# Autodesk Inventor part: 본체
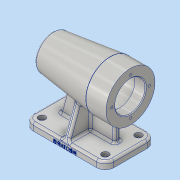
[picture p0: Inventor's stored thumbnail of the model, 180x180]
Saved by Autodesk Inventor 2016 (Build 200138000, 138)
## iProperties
Created: 2018-09
Part Number: 본체
Material: 알루미늄 6061
Document SubType Name: Modeling
Designer: 605-17
Density: 2.7 g/cm^3
Appearance: 알루미늄 - 평지
Mass: 731.151 g
Surface Area: 667.911 cm^2
Volume: 270.797 cm^3
Author: 605-17
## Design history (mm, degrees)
sketch "스케치2"
  geometry: L1 (-56, 35)-(56, 35); L2 (56, 35)-(56, -35); L3 (56, -35)-(-56, -35); L4 (-56, -35)-(-56, 35); 5 further points
  constraints: 8 end point, 4 horizontal alignment, 4 midpoint, 4 vertical alignment, 2 parallel, 1 horizontal, 1 perpendicular
  dimensions: "d0" = 112 distance of L1.start L1.end; "d1" = 70 distance of L3.end L1.start
extrude "돌출1" new body sketch "스케치2" distance "d2" = 10; taper "d3" = 0 deg
sketch "스케치3"
  geometry: L1 (56, 0)-(56, 10) reference; L2 (56, 74)-(-56, 74); L3 (-56, 74)-(-56, 108); L4 (-56, 108)-(-28, 108); L5 (-28, 108)-(52.27, 98.144); L6 (-56, 95)-(-41, 95); L7 (-41, 95)-(-41, 98); L8 (-41, 98)-(13, 98); L9 (13, 98)-(13, 95); L10 (13, 95)-(25, 95); L11 (25, 95)-(25, 91.5); L12 (25, 91.5)-(43, 91.5); L13 (43, 91.5)-(43, 90); L14 (43, 90)-(47, 90); L15 (47, 90)-(47, 84.5); L16 (47, 84.5)-(50, 84.5); L17 (50, 84.5)-(50, 74); A1 r 80 centre (-24, 74) between (52.27, 49.856) and (52.27, 98.144); 1 further point
  constraints: 32 end point, 11 perpendicular, 4 point on line, 3 point on circle, 2 vertical alignment, 1 centre point, 1 collinear, 1 horizontal, 1 horizontal alignment, 1 vertical
  dimensions: "d6" = 112 distance of L2.start L2.end; "d7" = 74 vertical distance of L2.start point (0, 0); "d9" = 7 deg angle of L5 L4; "d10" = 68 diameter of L4 L2; "d11" = 28 distance of L3.end L4.end; "d12" = 80 radius of A1; "d15" = 42 diameter of L6 L2; "d16" = 54 distance of L7.end L8.end; "d17" = 18 distance of L11.end L12.end; "d18" = 35 diameter of L12 L2; "d19" = 32 diameter of L14 L2; "d20" = 21 diameter of L16 L2; "d21" = 3 distance of L15.end L16.end; "d22" = 4 distance of L13.end L14.end; "d104" = 12 distance of L9.end L10.end; "d105" = 48 diameter of L8 L2; "d106" = 15 distance of L6.start L6.end
revolve "회전1" sketch "스케치3" stored, may be unused: angle "d23" = 90 deg
sketch "스케치4"
  geometry: C1 r 34 at (0, 0) reference; 2 further points
  constraints: 1 horizontal alignment
  dimensions: "d24" = 26 distance of C1.centre point (-26, 0)
hole "구멍1" sketch "스케치4" at (-26, 0) diameter "d25" = 3.242; stored, may be unused: countersink angle "d29" = 90 deg, drill point angle "d31" = 118 deg; dims "d26" = 8, "d27" = 4, "d28" = 2, "d30" = 11
fillet "모깎기1" dims "d35" = 12
fillet "모깎기2" dims "d36" = 3
sketch "스케치5"
  geometry: L1 (-35, 0)-(-35, 7) reference; L2 (35, 7)-(35, 0) reference; L3 (-34.819, 8.026)-(-18.467, 52.953); L4 (34.819, 8.026)-(18.467, 52.953); L5 (-23, 0)-(-35, 0) reference; L6 (-23, 0)-(23, 0) reference; L7 (35, 0)-(23, 0) reference; C1 r 24 at (0, 74) reference; A1 r 3 centre (-32, 7) between (-32, 10) and (-35, 7) reference; A2 r 3 centre (32, 7) between (35, 7) and (32, 10) reference; A3 r 28 centre (0, 74) between (-18.467, 52.953) and (18.467, 52.953); 1 further point
  constraints: 4 end point, 4 point on circle, 2 tangent, 1 centre point, 1 horizontal alignment
  dimensions: "d37" = 20 deg angle of L3 L1; "d38" = 28 radius of A3
extrude "돌출2" join sketch "스케치5" stored distance "d39" = 8; taper "d40" = 0 deg
sketch "스케치6"
  geometry: L1 (44, 10)-(4, 10) reference; L2 (44, 10)-(53, 10) reference; L3 (-4, 10)-(-44, 10) reference; L4 (-53, 10)-(-44, 10) reference; L5 (38, 10)-(27.282, 50); L6 (56, 0)-(56, 7) reference; L7 (-38, 10)-(-38, 43); L8 (-56, 7)-(-56, 0) reference; L9 (27.282, 50)-(-38, 43); L10 (38, 10)-(-38, 10); 1 further point
  constraints: 8 end point, 2 point on line, 1 horizontal, 1 vertical
  dimensions: "d41" = 105 deg angle of L5 L1; "d42" = 18 distance from line of L6 L5.start; "d43" = 18 distance between parallel lines of L8 L7; "d44" = 33 distance from line of L3 L7.end; "d45" = 40 distance from line of L1 L5.end
extrude "돌출3" join sketch "스케치6" stored distance "d46" = 8; taper "d47" = 0 deg
fillet "모깎기5" dims "d50" = 3
fillet "모깎기6" dims "d51" = 3
fillet "모깎기7" dims "d52" = 3
fillet "모깎기8" dims "d53" = 3
fillet "모깎기9" dims "d54" = 3
fillet "모깎기10" dims "d55" = 0.3
fillet "모깎기11" dims "d56" = 3
chamfer "모따기1" distance "d57" = 1; stored, may be unused: second distance "d58" = 2, angle "d59" = 45 deg
hole "구멍2" diameter "d62" = 5.5; stored, may be unused: countersink angle "d66" = 90 deg, drill point angle "d68" = 0 deg; dims "d60" = 10, "d61" = 10, "d63" = 8, "d64" = 9.5, "d65" = 5.4, "d67" = 11.8
hole "구멍3" diameter "d71" = 5.5; stored, may be unused: countersink angle "d75" = 90 deg, drill point angle "d77" = 0 deg; dims "d69" = 10, "d70" = 10, "d72" = 8, "d73" = 9.5, "d74" = 5.4, "d76" = 11.8
hole "구멍4" diameter "d80" = 5.5; stored, may be unused: countersink angle "d84" = 90 deg, drill point angle "d86" = 0 deg; dims "d78" = 10, "d79" = 10, "d81" = 8, "d82" = 9.5, "d83" = 5.4, "d85" = 11.8
hole "구멍5" diameter "d89" = 5.5; stored, may be unused: countersink angle "d93" = 90 deg, drill point angle "d95" = 0 deg; dims "d87" = 10, "d88" = 10, "d90" = 8, "d91" = 9.5, "d92" = 5.4, "d94" = 11.8
sketch "스케치7"
  geometry: L1 (-12, 7)-(-12, 0) reference; 2 further points
  constraints: 1 other
  dimensions: "d96" = 3 distance of point (44, 0) point (44, 3); "d97" = 56 distance from line of point (44, 3) L1
feature "엠보싱1" sketch "스케치7" dims "d0" = 112, "d1" = 70, "d98" = 0.5, "d99" = 0
fillet "모깎기12" dims "d100" = 3
node "솔리드1"
pattern_circular "원형 패턴1" dims angle "d33" = 360 deg
